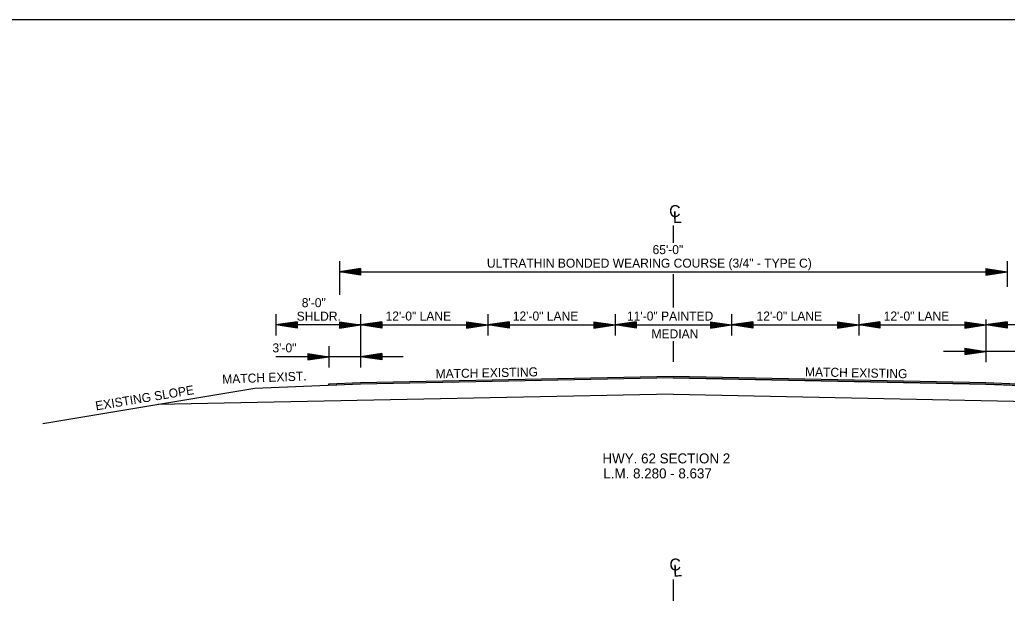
# Model space of a CAD drawing. Extents: x 2261938 to 2263136, y -3124572 to -3124216.
# Drawn here: x 2262700.3 to 2262793.4, y -3124501.1 to -3124446.1 of the extents above; entities that cross this region are included whole.
import ezdxf

# ---------------------------------------------------------------- set-up
doc = ezdxf.new("R2010")
doc.units = 0
for name, color, linetype in [('Default', 7, 'Continuous'), ('DSN_DRFT_Common-Annotations', 7, 'Continuous'), ('DSN_DRFT_Common-Line', 7, 'Continuous'), ('DSN_DRFT_Dimension', 7, 'Continuous')]:
    doc.layers.add(name, color=color, linetype=linetype)

msp = doc.modelspace()

# ---------------------------------------------------------------- linework, layer by layer
at = {"layer": 'DSN_DRFT_Common-Line'}
for p, q in [((2262761.939, -3124465.504), (2262761.939, -3124467.115)), ((2262730.439, -3124468.863), (2262730.439, -3124472.038)), ((2262793.439, -3124468.863), (2262793.439, -3124471.262)), ((2262761.939, -3124470.09), (2262761.939, -3124473.224)), ((2262724.439, -3124473.863), (2262724.439, -3124475.863)), ((2262732.439, -3124473.863), (2262732.439, -3124478.863)), ((2262744.439, -3124473.863), (2262744.439, -3124475.863)), ((2262756.439, -3124473.863), (2262756.439, -3124475.863)), ((2262767.439, -3124473.863), (2262767.439, -3124475.863)), ((2262779.439, -3124473.863), (2262779.439, -3124475.863)), ((2262791.439, -3124474.363), (2262791.439, -3124478.363)), ((2262761.939, -3124476.39), (2262761.939, -3124478.333)), ((2262729.439, -3124476.863), (2262729.439, -3124478.863)), ((2262761.939, -3124479.863), (2262732.439, -3124480.453)), ((2262761.939, -3124479.863), (2262791.439, -3124480.453)), ((2262722.439, -3124480.853), (2262702.439, -3124484.186)), ((2262732.439, -3124480.453), (2262722.439, -3124480.853)), ((2262729.439, -3124480.406), (2262729.439, -3124480.573)), ((2262791.439, -3124480.453), (2262801.439, -3124480.853)), ((2262761.939, -3124481.405), (2262713.291, -3124482.378)), ((2262761.939, -3124481.405), (2262810.587, -3124482.378)), ((2262761.939, -3124498.849), (2262761.939, -3124500.872))]:
    msp.add_line(p, q, dxfattribs=at)
for points in [[(2262676.902, -3124446.104), (2262676.902, -3124556.104), (2262846.902, -3124556.104), (2262846.902, -3124446.104)], [(2262791.439, -3124480.453), (2262761.939, -3124479.863), (2262732.439, -3124480.453), (2262729.439, -3124480.573), (2262729.439, -3124480.406), (2262732.439, -3124480.286), (2262761.939, -3124479.696), (2262791.439, -3124480.286), (2262794.439, -3124480.406), (2262794.439, -3124480.573)]]:
    msp.add_lwpolyline(points, close=True, dxfattribs=at)
at = {"layer": 'DSN_DRFT_Dimension'}
for p, q in [((2262732.439, -3124469.563), (2262730.439, -3124469.863)), ((2262732.439, -3124470.163), (2262730.439, -3124469.863)), ((2262730.439, -3124469.863), (2262793.439, -3124469.863)), ((2262732.439, -3124469.613), (2262730.773, -3124469.863)), ((2262732.439, -3124470.113), (2262730.773, -3124469.863)), ((2262732.439, -3124469.664), (2262731.117, -3124469.863)), ((2262732.439, -3124470.062), (2262731.117, -3124469.863)), ((2262732.439, -3124469.714), (2262731.45, -3124469.863)), ((2262732.439, -3124470.012), (2262731.45, -3124469.863)), ((2262732.439, -3124469.766), (2262731.789, -3124469.863)), ((2262732.439, -3124469.961), (2262731.789, -3124469.863)), ((2262732.439, -3124469.816), (2262732.123, -3124469.863)), ((2262732.439, -3124469.91), (2262732.123, -3124469.863)), ((2262732.439, -3124469.563), (2262732.439, -3124470.163)), ((2262791.439, -3124469.563), (2262793.439, -3124469.863)), ((2262791.439, -3124469.563), (2262791.439, -3124470.163)), ((2262791.439, -3124469.613), (2262793.105, -3124469.863)), ((2262791.439, -3124469.664), (2262792.761, -3124469.863)), ((2262791.439, -3124469.714), (2262792.428, -3124469.863)), ((2262791.439, -3124469.766), (2262792.089, -3124469.863)), ((2262791.439, -3124469.816), (2262791.755, -3124469.863)), ((2262791.439, -3124470.163), (2262793.439, -3124469.863)), ((2262791.439, -3124469.961), (2262792.089, -3124469.863)), ((2262791.439, -3124470.062), (2262792.761, -3124469.863)), ((2262791.439, -3124470.113), (2262793.105, -3124469.863)), ((2262791.439, -3124470.012), (2262792.428, -3124469.863)), ((2262791.439, -3124469.91), (2262791.755, -3124469.863)), ((2262726.439, -3124474.563), (2262724.439, -3124474.863)), ((2262726.439, -3124474.613), (2262724.773, -3124474.863)), ((2262726.439, -3124474.664), (2262725.117, -3124474.863)), ((2262726.439, -3124474.563), (2262726.439, -3124475.163)), ((2262730.439, -3124474.563), (2262732.439, -3124474.863)), ((2262730.439, -3124474.563), (2262730.439, -3124475.163)), ((2262730.439, -3124474.613), (2262732.105, -3124474.863)), ((2262730.439, -3124474.664), (2262731.761, -3124474.863)), ((2262734.439, -3124474.563), (2262732.439, -3124474.863)), ((2262734.439, -3124474.613), (2262732.773, -3124474.863)), ((2262734.439, -3124474.664), (2262733.117, -3124474.863)), ((2262734.439, -3124474.563), (2262734.439, -3124475.163)), ((2262742.439, -3124474.563), (2262744.439, -3124474.863)), ((2262742.439, -3124474.563), (2262742.439, -3124475.163)), ((2262742.439, -3124474.613), (2262744.105, -3124474.863)), ((2262742.439, -3124474.664), (2262743.761, -3124474.863)), ((2262746.439, -3124474.563), (2262744.439, -3124474.863)), ((2262746.439, -3124474.613), (2262744.773, -3124474.863)), ((2262746.439, -3124474.664), (2262745.117, -3124474.863)), ((2262746.439, -3124474.563), (2262746.439, -3124475.163)), ((2262754.439, -3124474.563), (2262756.439, -3124474.863)), ((2262754.439, -3124474.563), (2262754.439, -3124475.163)), ((2262754.439, -3124474.613), (2262756.105, -3124474.863)), ((2262754.439, -3124474.664), (2262755.761, -3124474.863)), ((2262758.439, -3124474.563), (2262756.439, -3124474.863)), ((2262758.439, -3124474.613), (2262756.773, -3124474.863)), ((2262758.439, -3124474.664), (2262757.117, -3124474.863)), ((2262758.439, -3124474.563), (2262758.439, -3124475.163)), ((2262765.439, -3124474.563), (2262767.439, -3124474.863)), ((2262765.439, -3124474.563), (2262765.439, -3124475.163)), ((2262765.439, -3124474.613), (2262767.105, -3124474.863)), ((2262765.439, -3124474.664), (2262766.761, -3124474.863)), ((2262769.439, -3124474.563), (2262767.439, -3124474.863)), ((2262769.439, -3124474.613), (2262767.773, -3124474.863)), ((2262769.439, -3124474.664), (2262768.117, -3124474.863)), ((2262769.439, -3124474.563), (2262769.439, -3124475.163)), ((2262777.439, -3124474.563), (2262779.439, -3124474.863)), ((2262777.439, -3124474.563), (2262777.439, -3124475.163)), ((2262777.439, -3124474.613), (2262779.105, -3124474.863)), ((2262777.439, -3124474.664), (2262778.761, -3124474.863)), ((2262781.439, -3124474.563), (2262779.439, -3124474.863)), ((2262781.439, -3124474.613), (2262779.773, -3124474.863)), ((2262781.439, -3124474.664), (2262780.117, -3124474.863)), ((2262781.439, -3124474.563), (2262781.439, -3124475.163)), ((2262789.439, -3124474.563), (2262791.439, -3124474.863)), ((2262789.439, -3124474.563), (2262789.439, -3124475.163)), ((2262789.439, -3124474.613), (2262791.105, -3124474.863)), ((2262789.439, -3124474.664), (2262790.761, -3124474.863)), ((2262793.439, -3124474.563), (2262791.439, -3124474.863)), ((2262793.439, -3124474.613), (2262791.773, -3124474.863)), ((2262793.439, -3124474.664), (2262792.117, -3124474.863)), ((2262793.439, -3124474.563), (2262793.439, -3124475.163)), ((2262732.439, -3124474.863), (2262724.439, -3124474.863)), ((2262726.439, -3124475.163), (2262724.439, -3124474.863)), ((2262726.439, -3124475.113), (2262724.773, -3124474.863)), ((2262726.439, -3124475.062), (2262725.117, -3124474.863)), ((2262726.439, -3124474.714), (2262725.45, -3124474.863)), ((2262726.439, -3124475.012), (2262725.45, -3124474.863)), ((2262726.439, -3124474.766), (2262725.789, -3124474.863)), ((2262726.439, -3124474.961), (2262725.789, -3124474.863)), ((2262726.439, -3124474.816), (2262726.123, -3124474.863)), ((2262726.439, -3124474.91), (2262726.123, -3124474.863)), ((2262730.439, -3124474.714), (2262731.428, -3124474.863)), ((2262730.439, -3124474.766), (2262731.089, -3124474.863)), ((2262730.439, -3124474.816), (2262730.755, -3124474.863)), ((2262730.439, -3124475.163), (2262732.439, -3124474.863)), ((2262730.439, -3124474.961), (2262731.089, -3124474.863)), ((2262730.439, -3124475.062), (2262731.761, -3124474.863)), ((2262730.439, -3124475.113), (2262732.105, -3124474.863)), ((2262730.439, -3124475.012), (2262731.428, -3124474.863)), ((2262730.439, -3124474.91), (2262730.755, -3124474.863)), ((2262732.439, -3124474.863), (2262744.439, -3124474.863)), ((2262734.439, -3124475.163), (2262732.439, -3124474.863)), ((2262734.439, -3124475.113), (2262732.773, -3124474.863)), ((2262734.439, -3124475.062), (2262733.117, -3124474.863)), ((2262734.439, -3124474.714), (2262733.45, -3124474.863)), ((2262734.439, -3124475.012), (2262733.45, -3124474.863)), ((2262734.439, -3124474.766), (2262733.789, -3124474.863)), ((2262734.439, -3124474.961), (2262733.789, -3124474.863)), ((2262734.439, -3124474.816), (2262734.123, -3124474.863)), ((2262734.439, -3124474.91), (2262734.123, -3124474.863)), ((2262742.439, -3124474.714), (2262743.428, -3124474.863)), ((2262742.439, -3124474.766), (2262743.089, -3124474.863)), ((2262742.439, -3124474.816), (2262742.755, -3124474.863)), ((2262742.439, -3124475.163), (2262744.439, -3124474.863)), ((2262742.439, -3124474.961), (2262743.089, -3124474.863)), ((2262742.439, -3124475.062), (2262743.761, -3124474.863)), ((2262742.439, -3124475.113), (2262744.105, -3124474.863)), ((2262742.439, -3124475.012), (2262743.428, -3124474.863)), ((2262742.439, -3124474.91), (2262742.755, -3124474.863)), ((2262744.439, -3124474.863), (2262756.439, -3124474.863)), ((2262746.439, -3124475.163), (2262744.439, -3124474.863)), ((2262746.439, -3124475.113), (2262744.773, -3124474.863)), ((2262746.439, -3124475.062), (2262745.117, -3124474.863)), ((2262746.439, -3124474.714), (2262745.45, -3124474.863)), ((2262746.439, -3124475.012), (2262745.45, -3124474.863)), ((2262746.439, -3124474.766), (2262745.789, -3124474.863)), ((2262746.439, -3124474.961), (2262745.789, -3124474.863)), ((2262746.439, -3124474.816), (2262746.123, -3124474.863)), ((2262746.439, -3124474.91), (2262746.123, -3124474.863)), ((2262754.439, -3124474.714), (2262755.428, -3124474.863)), ((2262754.439, -3124474.766), (2262755.089, -3124474.863)), ((2262754.439, -3124474.816), (2262754.755, -3124474.863)), ((2262754.439, -3124475.163), (2262756.439, -3124474.863)), ((2262754.439, -3124474.961), (2262755.089, -3124474.863)), ((2262754.439, -3124475.062), (2262755.761, -3124474.863)), ((2262754.439, -3124475.113), (2262756.105, -3124474.863)), ((2262754.439, -3124475.012), (2262755.428, -3124474.863)), ((2262754.439, -3124474.91), (2262754.755, -3124474.863)), ((2262756.439, -3124474.863), (2262767.439, -3124474.863)), ((2262758.439, -3124475.163), (2262756.439, -3124474.863)), ((2262758.439, -3124475.113), (2262756.773, -3124474.863)), ((2262758.439, -3124475.062), (2262757.117, -3124474.863)), ((2262758.439, -3124474.714), (2262757.45, -3124474.863)), ((2262758.439, -3124475.012), (2262757.45, -3124474.863)), ((2262758.439, -3124474.766), (2262757.789, -3124474.863)), ((2262758.439, -3124474.961), (2262757.789, -3124474.863)), ((2262758.439, -3124474.816), (2262758.123, -3124474.863)), ((2262758.439, -3124474.91), (2262758.123, -3124474.863)), ((2262765.439, -3124474.714), (2262766.428, -3124474.863)), ((2262765.439, -3124474.766), (2262766.089, -3124474.863)), ((2262765.439, -3124474.816), (2262765.755, -3124474.863)), ((2262765.439, -3124475.163), (2262767.439, -3124474.863)), ((2262765.439, -3124474.961), (2262766.089, -3124474.863)), ((2262765.439, -3124475.062), (2262766.761, -3124474.863)), ((2262765.439, -3124475.113), (2262767.105, -3124474.863)), ((2262765.439, -3124475.012), (2262766.428, -3124474.863)), ((2262765.439, -3124474.91), (2262765.755, -3124474.863)), ((2262767.439, -3124474.863), (2262779.439, -3124474.863)), ((2262769.439, -3124475.163), (2262767.439, -3124474.863)), ((2262769.439, -3124475.113), (2262767.773, -3124474.863)), ((2262769.439, -3124475.062), (2262768.117, -3124474.863)), ((2262769.439, -3124474.714), (2262768.45, -3124474.863)), ((2262769.439, -3124475.012), (2262768.45, -3124474.863)), ((2262769.439, -3124474.766), (2262768.789, -3124474.863)), ((2262769.439, -3124474.961), (2262768.789, -3124474.863)), ((2262769.439, -3124474.816), (2262769.123, -3124474.863)), ((2262769.439, -3124474.91), (2262769.123, -3124474.863)), ((2262777.439, -3124474.714), (2262778.428, -3124474.863)), ((2262777.439, -3124474.766), (2262778.089, -3124474.863)), ((2262777.439, -3124474.816), (2262777.755, -3124474.863)), ((2262777.439, -3124475.163), (2262779.439, -3124474.863)), ((2262777.439, -3124474.961), (2262778.089, -3124474.863)), ((2262777.439, -3124475.062), (2262778.761, -3124474.863)), ((2262777.439, -3124475.113), (2262779.105, -3124474.863)), ((2262777.439, -3124475.012), (2262778.428, -3124474.863)), ((2262777.439, -3124474.91), (2262777.755, -3124474.863)), ((2262779.439, -3124474.863), (2262791.439, -3124474.863)), ((2262781.439, -3124475.163), (2262779.439, -3124474.863)), ((2262781.439, -3124475.113), (2262779.773, -3124474.863)), ((2262781.439, -3124475.062), (2262780.117, -3124474.863)), ((2262781.439, -3124474.714), (2262780.45, -3124474.863)), ((2262781.439, -3124475.012), (2262780.45, -3124474.863)), ((2262781.439, -3124474.766), (2262780.789, -3124474.863)), ((2262781.439, -3124474.961), (2262780.789, -3124474.863)), ((2262781.439, -3124474.816), (2262781.123, -3124474.863)), ((2262781.439, -3124474.91), (2262781.123, -3124474.863)), ((2262789.439, -3124474.714), (2262790.428, -3124474.863)), ((2262789.439, -3124474.766), (2262790.089, -3124474.863)), ((2262789.439, -3124474.816), (2262789.755, -3124474.863)), ((2262789.439, -3124475.163), (2262791.439, -3124474.863)), ((2262789.439, -3124474.961), (2262790.089, -3124474.863)), ((2262789.439, -3124475.062), (2262790.761, -3124474.863)), ((2262789.439, -3124475.113), (2262791.105, -3124474.863)), ((2262789.439, -3124475.012), (2262790.428, -3124474.863)), ((2262789.439, -3124474.91), (2262789.755, -3124474.863)), ((2262799.439, -3124474.863), (2262791.439, -3124474.863)), ((2262793.439, -3124475.163), (2262791.439, -3124474.863)), ((2262793.439, -3124475.113), (2262791.773, -3124474.863)), ((2262793.439, -3124475.062), (2262792.117, -3124474.863)), ((2262793.439, -3124474.714), (2262792.45, -3124474.863)), ((2262793.439, -3124475.012), (2262792.45, -3124474.863)), ((2262793.439, -3124474.766), (2262792.789, -3124474.863)), ((2262793.439, -3124474.961), (2262792.789, -3124474.863)), ((2262793.439, -3124474.816), (2262793.123, -3124474.863)), ((2262793.439, -3124474.91), (2262793.123, -3124474.863)), ((2262799.439, -3124477.363), (2262787.439, -3124477.363)), ((2262789.439, -3124477.063), (2262791.439, -3124477.363)), ((2262789.439, -3124477.063), (2262789.439, -3124477.663)), ((2262789.439, -3124477.113), (2262791.105, -3124477.363)), ((2262789.439, -3124477.164), (2262790.761, -3124477.363)), ((2262789.439, -3124477.214), (2262790.428, -3124477.363)), ((2262789.439, -3124477.266), (2262790.089, -3124477.363)), ((2262789.439, -3124477.316), (2262789.755, -3124477.363)), ((2262789.439, -3124477.663), (2262791.439, -3124477.363)), ((2262789.439, -3124477.461), (2262790.089, -3124477.363)), ((2262789.439, -3124477.562), (2262790.761, -3124477.363)), ((2262789.439, -3124477.613), (2262791.105, -3124477.363)), ((2262789.439, -3124477.512), (2262790.428, -3124477.363)), ((2262789.439, -3124477.41), (2262789.755, -3124477.363)), ((2262736.439, -3124477.863), (2262724.439, -3124477.863)), ((2262727.439, -3124477.563), (2262729.439, -3124477.863)), ((2262727.439, -3124477.563), (2262727.439, -3124478.163)), ((2262727.439, -3124477.613), (2262729.105, -3124477.863)), ((2262727.439, -3124477.664), (2262728.761, -3124477.863)), ((2262727.439, -3124477.714), (2262728.428, -3124477.863)), ((2262727.439, -3124477.766), (2262728.089, -3124477.863)), ((2262727.439, -3124477.816), (2262727.755, -3124477.863)), ((2262727.439, -3124478.163), (2262729.439, -3124477.863)), ((2262727.439, -3124477.961), (2262728.089, -3124477.863)), ((2262727.439, -3124478.062), (2262728.761, -3124477.863)), ((2262727.439, -3124478.113), (2262729.105, -3124477.863)), ((2262727.439, -3124478.012), (2262728.428, -3124477.863)), ((2262727.439, -3124477.91), (2262727.755, -3124477.863)), ((2262734.439, -3124477.563), (2262732.439, -3124477.863)), ((2262734.439, -3124478.163), (2262732.439, -3124477.863)), ((2262734.439, -3124477.613), (2262732.773, -3124477.863)), ((2262734.439, -3124478.113), (2262732.773, -3124477.863)), ((2262734.439, -3124477.664), (2262733.117, -3124477.863)), ((2262734.439, -3124478.062), (2262733.117, -3124477.863)), ((2262734.439, -3124477.714), (2262733.45, -3124477.863)), ((2262734.439, -3124478.012), (2262733.45, -3124477.863)), ((2262734.439, -3124477.766), (2262733.789, -3124477.863)), ((2262734.439, -3124477.961), (2262733.789, -3124477.863)), ((2262734.439, -3124477.816), (2262734.123, -3124477.863)), ((2262734.439, -3124477.91), (2262734.123, -3124477.863)), ((2262734.439, -3124477.563), (2262734.439, -3124478.163))]:
    msp.add_line(p, q, dxfattribs=at)

# ---------------------------------------------------------------- texts
at = {"layer": 'Default'}
for s, p in [('C', (2262761.554, -3124464.713)), ('L', (2262761.904, -3124465.278)), ('C', (2262761.583, -3124498.021)), ('L', (2262761.933, -3124498.586))]:
    msp.add_text(s, height=1.124, rotation=1.14576, dxfattribs=at).set_placement(p)
at = {"layer": 'DSN_DRFT_Common-Annotations'}
for s, height, p in [('65\'-0"', 0.85, (2262759.981, -3124468.193)), ('ULTRATHIN BONDED WEARING COURSE (3/4" - TYPE C)', 0.85, (2262744.35, -3124469.468)), ('8\'-0"', 0.85, (2262726.883, -3124473.193)), ('SHLDR.', 0.85, (2262726.404, -3124474.468)), ('12\'-0" LANE', 0.85, (2262734.791, -3124474.453)), ('12\'-0" LANE', 0.85, (2262746.791, -3124474.453)), ('11\'-0" PAINTED', 0.85, (2262757.571, -3124474.453)), ('12\'-0" LANE', 0.85, (2262769.791, -3124474.453)), ('12\'-0" LANE', 0.85, (2262781.791, -3124474.453)), ('MEDIAN', 0.85, (2262759.881, -3124476.133)), (' 3\'-0"', 0.85, (2262723.801, -3124477.453)), ('HWY. 62 SECTION 2', 0.943, (2262755.256, -3124487.917)), ('L.M. 8.280 - 8.637', 0.943, (2262755.338, -3124489.331))]:
    msp.add_text(s, height=height, dxfattribs=at).set_placement(p)
for s, rotation, p in [('MATCH EXIST.', 2.29061, (2262719.393, -3124480.414)), ('MATCH EXISTING', 1.14576, (2262739.515, -3124479.902)), ('MATCH EXISTING', 358.85424, (2262774.358, -3124479.701)), ('EXISTING SLOPE', 9.462, (2262707.486, -3124482.929))]:
    msp.add_text(s, height=0.85, rotation=rotation, dxfattribs=at).set_placement(p)

doc.saveas('drawing.dxf')
